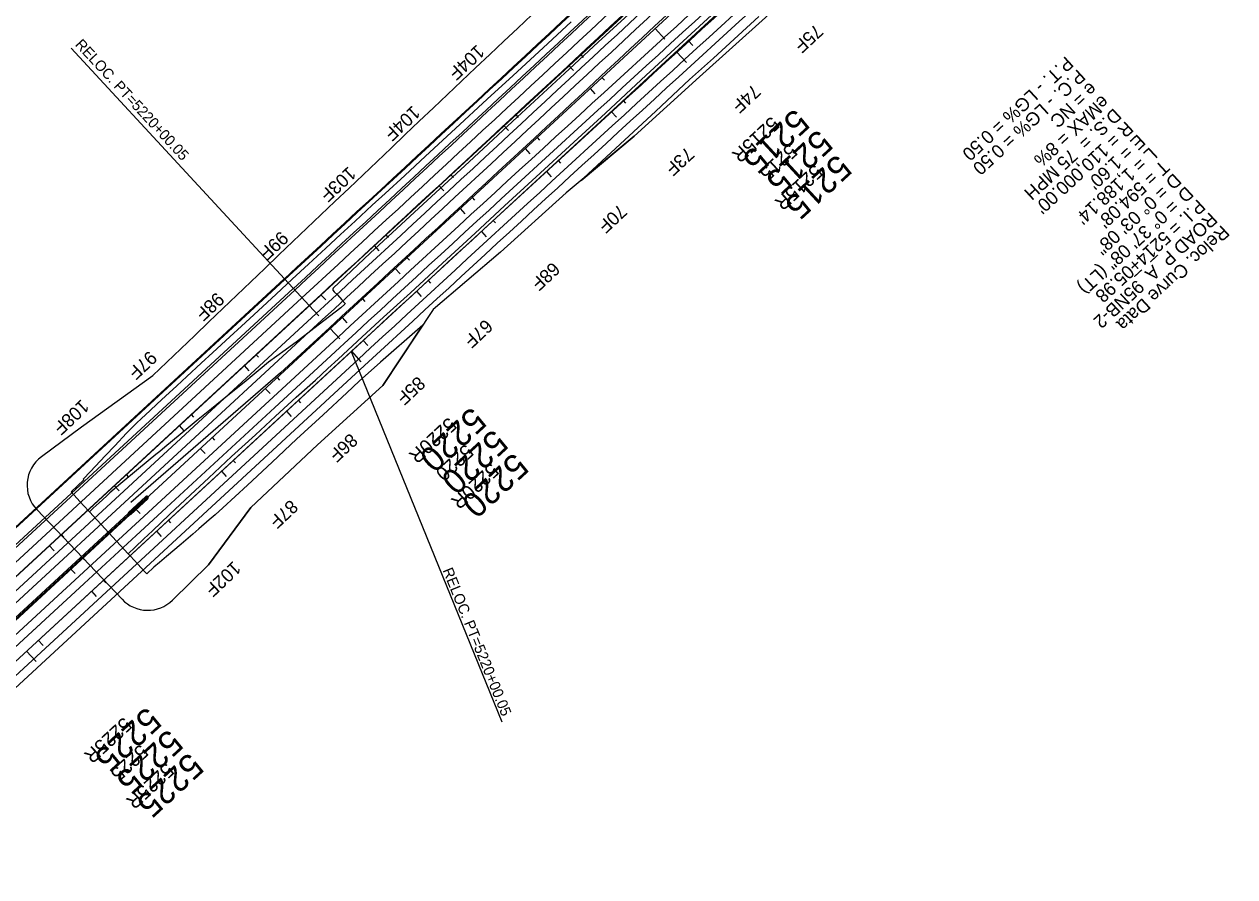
# Model space of a CAD drawing. Extents: x 2160876 to 2175990, y 601436 to 618246.
# Drawn here: x 2168336 to 2169705, y 609834 to 610799 of the extents above; entities that cross this region are included whole.
import ezdxf

# ---------------------------------------------------------------- set-up
doc = ezdxf.new("R2010")
doc.units = 0
for name, color, linetype in [('BNDY-ADJ', 7, 'Continuous'), ('BNDY-ADJ-TXT', 7, 'Continuous'), ('EX-UTIL-ELEC-TXT', 7, 'Continuous'), ('GN_Transparent 80', 7, 'Continuous'), ('RD_DTM_Major2', 7, 'Continuous'), ('RD_EX_BldgApp_Deck', 7, 'Continuous'), ('RD_EX_BldgApp_Sign', 7, 'Continuous'), ('RD_EX_BldgApp_Steps', 7, 'Continuous'), ('RD_EX_DV_TX_Prop', 7, 'Continuous'), ('RD_EX_Fence_Gate', 7, 'Continuous'), ('RD_EX_RW', 7, 'Continuous'), ('RD_HC_Cl', 7, 'Continuous'), ('RD_HC_Data_Tic', 7, 'Continuous'), ('RD_HC_TX_Sta50', 7, 'Continuous'), ('RD_TX_RoadID', 7, 'Continuous')]:
    doc.layers.add(name, color=color, linetype=linetype)

msp = doc.modelspace()

# ---------------------------------------------------------------- linework, layer by layer
at = {"layer": 'BNDY-ADJ'}
msp.add_line((2172239.9, 613739.9), (2163704.8, 605858.6), dxfattribs=at)
at = {"layer": 'BNDY-ADJ-TXT'}
for p, q in [((2168658.1, 610480.3), (2165572.4, 607631)), ((2168705.8, 610428.6), (2165620.1, 607579.3))]:
    msp.add_line(p, q, dxfattribs=at)
for centre, start, end in [((2094033.1, 691295.6), 312.719474, 313.338342), ((2243330.9, 529613.4), 132.100607, 132.719474)]:
    msp.add_arc(centre, 110000, start, end, dxfattribs=at)
at = {"layer": 'EX-UTIL-ELEC-TXT'}
for p, q in [((2168630.1, 610510.7), (2165544.4, 607661.4)), ((2168630.7, 610509.9), (2165545.1, 607660.6)), ((2168650, 610489.1), (2165564.3, 607639.8)), ((2168658.1, 610480.3), (2165572.4, 607631)), ((2168666.2, 610471.5), (2165580.6, 607622.2)), ((2168697.7, 610437.5), (2165612, 607588.1)), ((2168705.8, 610428.6), (2165620.1, 607579.3)), ((2168714, 610419.8), (2165628.3, 607570.5))]:
    msp.add_line(p, q, dxfattribs=at)
for centre, radius, start, end in [((2094033.1, 691295.6), 109958.7, 312.719474, 313.338342), ((2094033.1, 691295.6), 109959.7, 312.719474, 313.338342), ((2094033.1, 691295.6), 109988, 312.719474, 313.338342), ((2094033.1, 691295.6), 110000, 312.719474, 313.338342), ((2094033.1, 691295.6), 110012, 312.719474, 313.338342), ((2243330.9, 529613.4), 110012, 132.100607, 132.719474), ((2243330.9, 529613.4), 110000, 132.100607, 132.719474), ((2243330.9, 529613.4), 109988, 132.100607, 132.719474)]:
    msp.add_arc(centre, radius, start, end, dxfattribs=at)
at = {"layer": 'GN_Transparent 80'}
for p, q in [((2168640.2, 610499.7), (2165554.6, 607650.3)), ((2168641.8, 610497.9), (2165556.1, 607648.6)), ((2168454, 610245.6), (2165100.2, 607148.7)), ((2168455.6, 610243.9), (2165101.8, 607146.9)), ((2168455.6, 610243.9), (2168454, 610245.6))]:
    msp.add_line(p, q, dxfattribs=at)
for radius in [109973.7, 109976]:
    msp.add_arc((2094033.1, 691295.6), radius, 312.719474, 313.338342, dxfattribs=at)
at = {"layer": 'RD_DTM_Major2'}
for p, q in [((2169049.3, 610793.7), (2169060.2, 610781.9)), ((2168975.8, 610725.8), (2168981.3, 610720)), ((2168902.4, 610658), (2168907.8, 610652.1)), ((2168828.9, 610590.2), (2168834.3, 610584.3)), ((2168755.4, 610522.3), (2168760.9, 610516.4)), ((2168682, 610454.5), (2168692.8, 610442.7)), ((2168608.5, 610386.6), (2168613.9, 610380.8)), ((2168535, 610318.8), (2168540.5, 610312.9)), ((2168461.6, 610251), (2168467, 610245.1)), ((2168388.1, 610183.1), (2168393.5, 610177.2))]:
    msp.add_line(p, q, dxfattribs=at)
at = {"layer": 'RD_EX_BldgApp_Deck'}
for p, q in [((2168453.7, 610246), (2168473.5, 610264.3)), ((2168453.7, 610246), (2168473.5, 610264.3)), ((2168457, 610248.3), (2168473.9, 610263.9)), ((2168475.8, 610261.8), (2168473.5, 610264.3)), ((2168473.8, 610264), (2168473.5, 610264.3)), ((2168456, 610243.5), (2168475.8, 610261.8)), ((2168475.8, 610261.8), (2168456, 610243.5)), ((2168458.4, 610249.7), (2168457, 610248.3)), ((2168458.7, 610249.9), (2168458.4, 610249.7)), ((2168460, 610248), (2168458.4, 610249.7)), ((2168458.6, 610246.6), (2168475.5, 610262.2)), ((2168460.6, 610251.7), (2168458.7, 610249.9)), ((2168460.3, 610248.2), (2168458.7, 610249.9)), ((2168460.9, 610252), (2168460.6, 610251.7)), ((2168462.2, 610250), (2168460.6, 610251.7)), ((2168462.8, 610253.7), (2168460.9, 610252)), ((2168462.5, 610250.3), (2168460.9, 610252)), ((2168463.1, 610254), (2168462.8, 610253.7)), ((2168464.4, 610252), (2168462.8, 610253.7)), ((2168465.1, 610255.8), (2168463.1, 610254)), ((2168464.7, 610252.3), (2168463.1, 610254)), ((2168465.3, 610256), (2168465.1, 610255.8)), ((2168466.6, 610254.1), (2168465.1, 610255.8)), ((2168467.3, 610257.8), (2168465.3, 610256)), ((2168466.9, 610254.3), (2168465.3, 610256)), ((2168467.5, 610258.1), (2168467.3, 610257.8)), ((2168468.8, 610256.1), (2168467.3, 610257.8)), ((2168469.5, 610259.8), (2168467.5, 610258.1)), ((2168469.1, 610256.4), (2168467.5, 610258.1)), ((2168469.8, 610260.1), (2168469.5, 610259.8)), ((2168471, 610258.1), (2168469.5, 610259.8)), ((2168471.7, 610261.9), (2168469.8, 610260.1)), ((2168471.3, 610258.4), (2168469.8, 610260.1)), ((2168473.2, 610260.2), (2168471.7, 610261.9)), ((2168473.5, 610260.4), (2168472, 610262.1)), ((2168475.8, 610261.8), (2168475.5, 610262.1)), ((2168453.7, 610246), (2168454, 610245.6)), ((2168454, 610245.6), (2168453.7, 610246)), ((2168454, 610245.6), (2168457, 610248.3)), ((2168457, 610248.3), (2168454, 610245.6)), ((2168455.6, 610243.9), (2168458.6, 610246.6)), ((2168455.6, 610243.9), (2168458.6, 610246.6)), ((2168456, 610243.5), (2168455.6, 610243.9)), ((2168456, 610243.5), (2168455.6, 610243.9)), ((2168458.6, 610246.6), (2168457, 610248.3))]:
    msp.add_line(p, q, dxfattribs=at)
for points in [[(2168473.9, 610263.9), (2168472, 610262.1), (2168471.7, 610261.9)], [(2168473.5, 610264.3), (2168473.8, 610264), (2168473.9, 610263.9)], [(2168458.6, 610246.6), (2168460, 610248), (2168460.3, 610248.2), (2168462.2, 610250), (2168462.5, 610250.3), (2168464.4, 610252), (2168464.7, 610252.3), (2168466.6, 610254.1), (2168466.9, 610254.3), (2168468.8, 610256.1), (2168469.1, 610256.4), (2168471, 610258.1), (2168471.3, 610258.4), (2168473.2, 610260.2), (2168473.5, 610260.4), (2168475.5, 610262.2)], [(2168475.5, 610262.2), (2168475.5, 610262.1), (2168475.8, 610261.8)]]:
    msp.add_lwpolyline(points, dxfattribs=at)
for radius in [1.67, 1.67, 1.27, 1.27]:
    msp.add_arc((2168474.7, 610263.1), radius, 312.7195, 132.7195, dxfattribs=at)
at = {"layer": 'RD_EX_BldgApp_Sign'}
for p, q in [((2168681.2, 610455.3), (2168625.9, 610404.3)), ((2168625.9, 610404.3), (2168456.6, 610257.5))]:
    msp.add_line(p, q, dxfattribs=at)
msp.add_arc((2094033.1, 691295.6), 110034, 312.719474, 313.338342, dxfattribs=at)
at = {"layer": 'RD_EX_BldgApp_Steps'}
for p, q in [((2172672.7, 614139.6), (2163700.6, 605854.7)), ((2169773.5, 611510.3), (2165657.1, 607709.2)), ((2169821.3, 611458.6), (2165682.4, 607636.8)), ((2169086.6, 610780.2), (2169092, 610774.4)), ((2168965.4, 610764.1), (2168968.1, 610761.1)), ((2168989.2, 610738.2), (2168992, 610735.3)), ((2169013.1, 610712.4), (2169015.8, 610709.4)), ((2168891.9, 610696.2), (2168894.6, 610693.3)), ((2168915.8, 610670.4), (2168918.5, 610667.4)), ((2168939.6, 610644.5), (2168942.3, 610641.6)), ((2168818.5, 610628.4), (2168821.2, 610625.4)), ((2168842.3, 610602.5), (2168845, 610599.6)), ((2168866.2, 610576.7), (2168868.9, 610573.8)), ((2168745, 610560.5), (2168747.7, 610557.6)), ((2168768.8, 610534.7), (2168771.6, 610531.8)), ((2168792.7, 610508.9), (2168795.4, 610505.9)), ((2168671.5, 610492.7), (2168676.9, 610486.8)), ((2168718.3, 610488), (2168721, 610485.1)), ((2168695.4, 610466.9), (2168700.8, 610461)), ((2168719.2, 610441), (2168724.7, 610435.1)), ((2168598, 610424.9), (2168600.8, 610421.9)), ((2168621.9, 610399), (2168624.6, 610396.1)), ((2168645.8, 610373.2), (2168648.5, 610370.2)), ((2168524.6, 610357), (2168527.3, 610354.1)), ((2168548.4, 610331.2), (2168551.1, 610328.2)), ((2168572.3, 610305.3), (2168575, 610302.4)), ((2168451.1, 610289.2), (2168453.8, 610286.2)), ((2168498.8, 610237.5), (2168501.5, 610234.6)), ((2168377.6, 610221.3), (2168380.4, 610218.4)), ((2168401.5, 610195.5), (2168404.2, 610192.6)), ((2168425.4, 610169.7), (2168428.1, 610166.7)), ((2168351.9, 610101.8), (2168357.3, 610095.9))]:
    msp.add_line(p, q, dxfattribs=at)
at = {"layer": 'RD_EX_Fence_Gate'}
for p, q in [((2168446.6, 610148.2), (2168350.2, 610249.6)), ((2168544.5, 610187.1), (2168503.5, 610147.1))]:
    msp.add_line(p, q, dxfattribs=at)
for points in [[(2169947.4, 611516.2), (2169906.8, 611486.5), (2169832.2, 611419.8), (2169766.1, 611344.1), (2169692.9, 611276), (2169621.4, 611206), (2169538.3, 611148.5), (2169467, 611078.3), (2169391.8, 611012.4), (2169318.6, 610944.2), (2169284.7, 610907.2), (2169174, 610806.1), (2169099.5, 610739.3), (2169025.5, 610672), (2168948.7, 610607.8), (2168874.4, 610540.9), (2168798.4, 610475.8), (2168741.5, 610390), (2168667.6, 610322.7), (2168592.4, 610252), (2168544.5, 610187.1)], [(2168481.4, 610401.1), (2168400.7, 610342.8), (2168355.4, 610309.3)]]:
    msp.add_lwpolyline(points, dxfattribs=at)
for centre, radius, start, end in [((2219097.5, 557675.8), 73088.7, 133.280708, 133.830736), ((2168379.2, 610277.1), 40, 126.5043, 223.5367), ((2168475.6, 610175.7), 40, 223.5367, 314.3005)]:
    msp.add_arc(centre, radius, start, end, dxfattribs=at)
at = {"layer": 'RD_EX_RW'}
for p, q in [((2168968.3, 610624.4), (2168965.7, 610622)), ((2168350.2, 610249.6), (2168446.6, 610148.2)), ((2168424.5, 610260.7), (2168420.9, 610257.4)), ((2168453.7, 610199.4), (2168409.7, 610247.2)), ((2168453.7, 610199.4), (2168409.7, 610247.2)), ((2168409.7, 610247.2), (2168453.7, 610199.4)), ((2168456, 610197), (2168453.7, 610199.4)), ((2168503.5, 610147.1), (2168544.5, 610187.1))]:
    msp.add_line(p, q, dxfattribs=at)
for points in [[(2168965.7, 610622), (2169025.5, 610672), (2169099.5, 610739.3), (2169174, 610806.1), (2169284.7, 610907.2), (2169318.6, 610944.2), (2169391.8, 611012.4), (2169467, 611078.3), (2169538.3, 611148.5), (2169621.4, 611206), (2169692.9, 611276), (2169766.1, 611344.1), (2169824.9, 611411.5)], [(2169075.5, 610861.4), (2168985.1, 610778.3), (2168947.4, 610743.2), (2168893.5, 610693.5), (2168839, 610643), (2168782.2, 610590.5), (2168727.3, 610539.6), (2168685.2, 610500.1), (2168685, 610499.1), (2168685.1, 610497.8), (2168686.4, 610496.1), (2168690.2, 610492.4), (2168695.1, 610487), (2168698.7, 610482.9), (2168698.4, 610482), (2168693.9, 610477.9), (2168674.7, 610463), (2168660.1, 610451.9), (2168645, 610440), (2168630.9, 610429.8), (2168612.3, 610416.2), (2168602.7, 610408.4), (2168584.7, 610393.4), (2168570.1, 610381.6), (2168547.7, 610363.7), (2168532.6, 610351.6), (2168512.3, 610334.7), (2168494.8, 610320.1), (2168489.2, 610315.5), (2168484.9, 610312.1), (2168465.3, 610295.6), (2168445.3, 610279.1), (2168432.7, 610268.5), (2168429.6, 610265.7), (2168424.5, 610260.7)], [(2168453.7, 610199.4), (2168461.6, 610207), (2168471.4, 610216.5), (2168480.9, 610225.6), (2168500.4, 610244), (2168523.9, 610266.4), (2168544.7, 610285.6), (2168570.4, 610309.7), (2168597.4, 610334.3), (2168620.2, 610355.2), (2168643.6, 610376.7), (2168665.2, 610396), (2168679.2, 610409.1), (2168690.8, 610419.9), (2168718.2, 610445), (2168742.4, 610467.1), (2168772.9, 610494.8), (2168808.9, 610528.3), (2168845.8, 610562.4), (2168879.2, 610593.3), (2168915, 610626.1), (2168957.3, 610665.4), (2168993.2, 610698.2), (2169039.2, 610741.2), (2169085.5, 610783.5), (2169131.6, 610826.1)], [(2168403.5, 610283.3), (2168402.9, 610284.4), (2168410.6, 610292.2), (2168428, 610310.8), (2168438.4, 610321.9), (2168451.5, 610336), (2168458.1, 610342.6), (2168462.9, 610347.3), (2168468.5, 610352.5), (2168478.1, 610361.3), (2168486.5, 610369.2), (2168495.8, 610377.9), (2168508.6, 610389.7), (2168519.9, 610400.3), (2168536.1, 610415.2), (2168549.3, 610427.3), (2168568.4, 610444.9), (2168581.6, 610457), (2168600.4, 610474.6), (2168620.7, 610493.2), (2168626.8, 610498.9), (2168639, 610510.2), (2168657.4, 610527.1), (2168677.2, 610545.3), (2168693.6, 610560.6), (2168710.1, 610576), (2168729.6, 610593.9), (2168744.3, 610607.2), (2168766.2, 610627.5), (2168789.9, 610649.3), (2168823.8, 610680.8), (2168859.4, 610713.7), (2168888.9, 610740.8), (2168922.8, 610772), (2168954.6, 610801.5)], [(2169166.6, 610807.4), (2169115.3, 610760.4), (2169088.2, 610736), (2169050.2, 610700.3), (2169009.8, 610663.1), (2168968.3, 610624.4)], [(2168786.7, 610458.2), (2168783.7, 610455.5), (2168739, 610416.5), (2168714.8, 610394.8), (2168700.7, 610381.6), (2168674, 610356.9), (2168643.7, 610329.1), (2168616.2, 610303.3), (2168588.4, 610277.3), (2168560.7, 610251.6), (2168552, 610243.7), (2168545.2, 610238.1), (2168533.5, 610227.7), (2168526.8, 610221.7), (2168513.5, 610210.6), (2168496.7, 610196.5), (2168489, 610189.8), (2168482.7, 610184.4), (2168474.6, 610177), (2168473.9, 610177.6), (2168472.3, 610179.3)], [(2168544.5, 610187.1), (2168592.4, 610252), (2168667.6, 610322.7), (2168741.5, 610390), (2168786.7, 610458.2)], [(2168481.4, 610401.1), (2168400.7, 610342.8), (2168355.4, 610309.3)], [(2168409.7, 610247.2), (2168408.8, 610248.1), (2168398.9, 610258.8), (2168389, 610269.6), (2168403.5, 610283.3)], [(2168420.9, 610257.4), (2168414, 610251.1), (2168414, 610251.1), (2168409.7, 610247.2)], [(2168472.3, 610179.3), (2168464.6, 610187.7), (2168464.4, 610187.9), (2168456, 610197)]]:
    msp.add_lwpolyline(points, dxfattribs=at)
for centre, radius, start, end in [((2219097.5, 557675.8), 73088.7, 133.280708, 133.830736), ((2168379.2, 610277.1), 40, 126.5043, 223.5367), ((2168475.6, 610175.7), 40, 223.5367, 314.3005)]:
    msp.add_arc(centre, radius, start, end, dxfattribs=at)
at = {"layer": 'RD_HC_Cl'}
for p, q in [((2169074, 610767), (2169084.8, 610755.2)), ((2168951.5, 610752.2), (2168957, 610746.4)), ((2169000.2, 610699.5), (2169005.6, 610693.6)), ((2168878.3, 610684.2), (2168883.7, 610678.3)), ((2168926.5, 610631.9), (2168931.9, 610626)), ((2168804.9, 610616.2), (2168810.4, 610610.3)), ((2168852.9, 610564.2), (2168858.3, 610558.3)), ((2168731.6, 610548.2), (2168737, 610542.3)), ((2168779.4, 610496.5), (2168784.8, 610490.6)), ((2168658.1, 610480.3), (2168669, 610468.6)), ((2168705.9, 610428.7), (2168716.7, 610416.9)), ((2168584.7, 610412.5), (2168590.1, 610406.6)), ((2168632.4, 610360.8), (2168637.8, 610355)), ((2168511.2, 610344.7), (2168516.6, 610338.8)), ((2168558.9, 610293), (2168564.3, 610287.1)), ((2168437.7, 610276.8), (2168443.2, 610270.9)), ((2168485.4, 610225.1), (2168490.9, 610219.3)), ((2168364.3, 610209), (2168369.7, 610203.1)), ((2168412, 610157.3), (2168417.4, 610151.4)), ((2168338.5, 610089.5), (2168349.4, 610077.7))]:
    msp.add_line(p, q, dxfattribs=at)
at = {"layer": 'RD_HC_TX_Sta50'}
for p, q in [((2168658.1, 610480.3), (2168389, 610771.7)), ((2168705.8, 610428.6), (2168876, 610009.4))]:
    msp.add_line(p, q, dxfattribs=at)
at = {"layer": 'RD_TX_RoadID'}
for p, q in [((2168641.8, 610497.9), (2165556.1, 607648.6)), ((2168673, 610464.1), (2165587.4, 607614.8)), ((2168690.9, 610444.8), (2165605.2, 607595.5)), ((2168720.7, 610412.5), (2165635.1, 607563.2))]:
    msp.add_line(p, q, dxfattribs=at)
for centre, radius, start, end in [((2094033.1, 691295.6), 109976, 312.719474, 313.338342), ((2094033.1, 691295.6), 110022, 312.719474, 313.338342), ((2243330.9, 529613.4), 110022, 132.100607, 132.719474), ((2243330.9, 529613.4), 109978, 132.100607, 132.719474)]:
    msp.add_arc(centre, radius, start, end, dxfattribs=at)

# ---------------------------------------------------------------- texts
at = {"layer": 'RD_EX_BldgApp_Steps'}
for s, p in [('5215', (2169207.4, 610704.4)), ('5215', (2169233.7, 610680.9)), ('5215', (2169255.1, 610652.8)), ('5220', (2168842, 610367)), ('5220', (2168866.5, 610341.8)), ('5220', (2168889.7, 610315.3)), ('5225', (2168474.6, 610027.7)), ('5225', (2168499.1, 610002.5)), ('5225', (2168522.3, 609976.1))]:
    msp.add_text(s, height=28, rotation=222.7195, dxfattribs=at).set_placement(p)
at = {"layer": 'RD_EX_DV_TX_Prop'}
for s, p in [('5215', (2169201, 610664.3)), ('5220', (2168834.8, 610324.6)), ('5225', (2168467.1, 609985))]:
    msp.add_text(s, height=16, rotation=222.7195, dxfattribs=at).set_placement(p)
at = {"layer": 'RD_EX_Fence_Gate'}
for s, rotation, p in [('75F', 222.7518, (2169230.7, 610799.6)), ('104F', 222.9873, (2168847.9, 610776.4)), ('74F', 222.8303, (2169160.1, 610731.5)), ('104F', 223.0658, (2168775.2, 610707.5)), ('73F', 222.9088, (2169084.9, 610660.6)), ('103F', 223.1443, (2168702.6, 610638.6)), ('70F', 222.9873, (2169008.8, 610595.8)), ('99F', 223.2228, (2168626, 610565.6)), ('68F', 223.0658, (2168933.2, 610530.6)), ('98F', 223.3012, (2168553.5, 610496.4)), ('67F', 223.1443, (2168857.1, 610465.9)), ('97F', 223.3797, (2168477.4, 610430.2)), ('85F', 223.2228, (2168780.8, 610401.3)), ('108F', 223.4582, (2168400.7, 610375.2)), ('86F', 223.3012, (2168704.4, 610336.8)), ('87F', 223.3797, (2168636.9, 610261.7)), ('102F', 223.4582, (2168572.4, 610192.2))]:
    msp.add_text(s, height=15, rotation=rotation, dxfattribs=at).set_placement(p)
at = {"layer": 'RD_HC_Data_Tic'}
for s, rotation, p in [('5215R', 222.9799, (2169180.8, 610695.2)), ('5215R', 222.459, (2169229.6, 610641)), ('5220R', 222.7195, (2168815.8, 610354.9)), ('5220R', 222.7194, (2168863.5, 610303.2)), ('5225R', 222.7195, (2168448.5, 610015.7)), ('5225R', 222.7195, (2168496.2, 609964))]:
    msp.add_text(s, height=16, rotation=rotation, dxfattribs=at).set_placement(p)
at = {"layer": 'RD_HC_TX_Sta50'}
for s, height, rotation, p in [('RELOC. PT=5220+00.05', 12, 312.7195, (2168392.8, 610775.1)), ('P.T. - LG% = 0.50', 15, 222.7195, (2169513.7, 610763.2)), ('P.C. - LG% = 0.50', 15, 222.7195, (2169527.2, 610748.6)), ('e = NC', 15, 222.7195, (2169540.8, 610733.9)), ('eMAX = 8%', 15, 222.7195, (2169554.4, 610719.2)), ('D.S. =  75 MPH', 15, 222.7195, (2169568, 610704.5)), ("R = 110,000.00'", 15, 222.7195, (2169581.5, 610689.8)), ("E = 1.60'", 15, 222.7195, (2169595.1, 610675.1)), ("L = 1,188.14'", 15, 222.7195, (2169608.7, 610660.4)), ("T = 594.08'", 15, 222.7195, (2169622.2, 610645.7)), ('D = 0° 03\' 08"', 15, 222.7195, (2169635.8, 610631)), ('D', 15, 222.7195, (2169649.4, 610616.3)), ('    = 0° 37\' 08" (LT)', 15, 222.7195, (2169649.4, 610616.3)), ('P.I. = 5214+05.98', 15, 222.7195, (2169662.9, 610601.6)), ('ROAD P_A_95NB-2', 15, 222.7195, (2169676.5, 610586.9)), ('Reloc. Curve Data', 15, 222.7195, (2169690.1, 610572.2)), ('RELOC. PT=5220+00.05', 12, 292.0972, (2168808.8, 610181))]:
    msp.add_text(s, height=height, rotation=rotation, dxfattribs=at).set_placement(p)

doc.saveas('drawing.dxf')
